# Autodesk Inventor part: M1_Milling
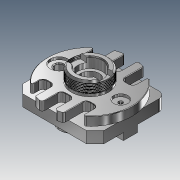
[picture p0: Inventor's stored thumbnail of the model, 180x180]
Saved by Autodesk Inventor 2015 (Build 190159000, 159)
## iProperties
Created: 2015-04
Part Number: M1_Milling
Material: Alumínio 6061
Document SubType Name: Modeling
Designer: Andrew Almeida
Density: 2.7 g/cm^3
Appearance: Alumínio - Plano
Title: C:/Users/Andrew Almeida/Documents/Projeto WS2015/WS2015 CAD Data ANLAS/07/#07 - CNC Milling/01 - 3D Models/M1_Milling.stp
Creation Date: 2015-04-23
Sending System: Autodesk Translation Framework v4.0.0.5211
Preprocessor: ST-DEVELOPER v16.1
Author: Andrew Almeida
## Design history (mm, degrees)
node "M1_Milling1"
feature "Rosca1" dims "d0" = 10, "d1" = 0
sketch "Esboço2"
  geometry: L1 (21, 0)-(21, 10); L2 (21, 10)-(20.259, 10); L3 (20.259, 10)-(20.259, 0); L4 (20.259, 0)-(21, 0); L5 (0, -11.3)-(0, 53.8) reference
  constraints: 8 end point
revolve "Revolução1" sketch "Esboço2" stored, may be unused: angle "d11" = 0 deg
sketch "Esboço3"
  geometry: L1 (21, 0)-(21, 10); L2 (21, 10)-(20.259, 10); L3 (20.259, 10)-(20.259, 0); L4 (20.259, 0)-(21, 0); L5 (0, -11.3)-(0, 53.8) reference
  constraints: 8 end point
revolve "Revolução2" sketch "Esboço3" stored, may be unused: angle "d12" = 0 deg
sketch "Esboço1"
  geometry: L1 (-0.583, -20.309)-(-0.5, -20.309); L2 (0.083, -20.95)-(0, -21.11); L3 (-1, -21.11)-(-1.083, -20.95); L4 (-0.417, -20.309)-(-0.5, -20.149); L5 (-0.5, -20.149)-(-0.583, -20.309); L6 (-1, -21.11)-(-0.917, -20.95); L7 (-0.417, -20.309)-(-0.083, -20.95); L8 (-1.083, -20.95)-(-0.917, -20.95); L9 (0.083, -20.95)-(-0.083, -20.95); L10 (-1, -21.11)-(-1, -20.95); L11 (0, -21.11)-(0, -20.95); L12 (-0.5, -20.149)-(-0.5, -20.259); L13 (-1, -21)-(0, -21); L14 (-0.083, -20.95)-(0, -21.11); L15 (-0.917, -20.95)-(-0.583, -20.309); L16 (0, 0)-(0, 0.018); L17 (0, 0.018)-(0, 0); L18 (0, 0)-(0.033, 0); L19 (-0.5, -20.259)-(-0.5, -20.309); L20 (-0.5, -20.309)-(-0.417, -20.309); A1 r 0.094 centre (-1, -20.906) between (-1.083, -20.95) and (-1, -21); A2 r 0.094 centre (-1, -20.906) between (-1, -21) and (-0.917, -20.95); A3 r 0.094 centre (0, -20.906) between (-0.083, -20.95) and (0, -21); A4 r 0.094 centre (0, -20.906) between (0, -21) and (0.083, -20.95); A5 r 0.094 centre (-0.5, -20.353) between (-0.5, -20.259) and (-0.583, -20.309); A6 r 0.094 centre (-0.5, -20.353) between (-0.417, -20.309) and (-0.5, -20.259)
  constraints: 40 end point, 12 point on circle, 10 parallel, 8 tangent, 6 centre point, 6 collinear, 2 midpoint, 2 point on line, 1 horizontal, 1 perpendicular, 3 other
  dimensions: "d2" = 55 deg angle of L7 L15 (= d9); "d3" = 0.16008 distance of L4.end L1.end (= 0.160083 x Esboço1_Pitch); "d4" = 0.16008 distance of L2.end L11.end (= 0.160083 x Esboço1_Pitch); "Esboço1_ThreadOffset" = 0 distance between parallel lines of L16 L11; "Esboço1_MajorRadius" = 21 distance from line of L13 L16.start; "d7" = 1 distance from line of L2.end L10 (= Esboço1_Pitch); "Esboço1_MinorRadius" = 20.25854 distance edge to line of A6 L18 (derived)
feature "Espiral1" sketch "Esboço1" pitch "d13" = 1.5015; turns "d15" = 1; dims "d14" = 13, "d16" = 0, angle "d17" = 0 deg, angle "d18" = 0 deg, "d19" = 0, "d20" = 0
feature "Rosca2" dims "d21" = 10, "d22" = 0
sketch "Esboço5"
  geometry: L1 (2.458, 0)-(2.458, 14.1); L2 (2.458, 14.1)-(1.717, 14.1); L3 (1.717, 14.1)-(1.717, 0); L4 (1.717, 0)-(2.458, 0); L5 (0, -27.3)-(0, 37.8) reference
  constraints: 8 end point
revolve "Revolução3" sketch "Esboço5" stored, may be unused: angle "d32" = 0 deg
sketch "Esboço4"
  geometry: L1 (-0.583, -0.051)-(-0.5, -0.051); L2 (0.083, -0.691)-(0, -0.851); L3 (-1, -0.851)-(-1.083, -0.691); L4 (-0.417, -0.051)-(-0.5, 0.109); L5 (-0.5, 0.109)-(-0.583, -0.051); L6 (-1, -0.851)-(-0.917, -0.691); L7 (-0.417, -0.051)-(-0.083, -0.691); L8 (-1.083, -0.691)-(-0.917, -0.691); L9 (0.083, -0.691)-(-0.083, -0.691); L10 (-1, -0.851)-(-1, -0.691); L11 (0, -0.851)-(0, -0.691); L12 (-0.5, 0.109)-(-0.5, 0); L13 (-1, -0.742)-(0, -0.742); L14 (-0.083, -0.691)-(0, -0.851); L15 (-0.917, -0.691)-(-0.583, -0.051); L16 (0, 0)-(0, 0.018); L17 (0, 0.018)-(0, 0); L18 (0, 0)-(0.033, 0); L19 (-0.5, 0)-(-0.5, -0.051); L20 (-0.5, -0.051)-(-0.417, -0.051); A1 r 0.094 centre (-1, -0.648) between (-1.083, -0.691) and (-1, -0.742); A2 r 0.094 centre (-1, -0.648) between (-1, -0.742) and (-0.917, -0.691); A3 r 0.094 centre (0, -0.648) between (-0.083, -0.691) and (0, -0.742); A4 r 0.094 centre (0, -0.648) between (0, -0.742) and (0.083, -0.691); A5 r 0.094 centre (-0.5, -0.094) between (-0.5, 0) and (-0.583, -0.051); A6 r 0.094 centre (-0.5, -0.094) between (-0.417, -0.051) and (-0.5, 0)
  constraints: 40 end point, 12 point on circle, 10 parallel, 8 tangent, 6 centre point, 6 collinear, 2 midpoint, 2 point on line, 1 horizontal, 1 perpendicular, 3 other
  dimensions: "d23" = 55 deg angle of L7 L15 (= d30); "d24" = 0.16008 distance of L4.end L1.end (= 0.160083 x Esboço4_Pitch); "d25" = 0.16008 distance of L2.end L11.end (= 0.160083 x Esboço4_Pitch); "Esboço4_ThreadOffset" = 0 distance between parallel lines of L16 L11; "Esboço4_MajorRadius" = 0.74146 distance from line of L13 L16.start; "d28" = 1 distance from line of L2.end L10 (= Esboço4_Pitch); "Esboço4_MinorRadius" = 0 distance edge to line of A6 L18 (derived)
feature "Espiral2" sketch "Esboço4" pitch "d33" = 1.001; turns "d35" = 1; dims "d34" = 16.1, "d36" = 0, angle "d37" = 0 deg, angle "d38" = 0 deg, "d39" = 0, "d40" = 0
node "Body1"
node "Base1"
node "Sólido2"
node "Sólido3"
other parameters: "d9" = 55 deg [user parameter; used in 1 equation term], "Esboço1_Pitch" = 1 [user parameter; used in 3 equation terms], "d30" = 55 deg [user parameter; used in 1 equation term], "Esboço4_Pitch" = 1 [user parameter; used in 3 equation terms]
